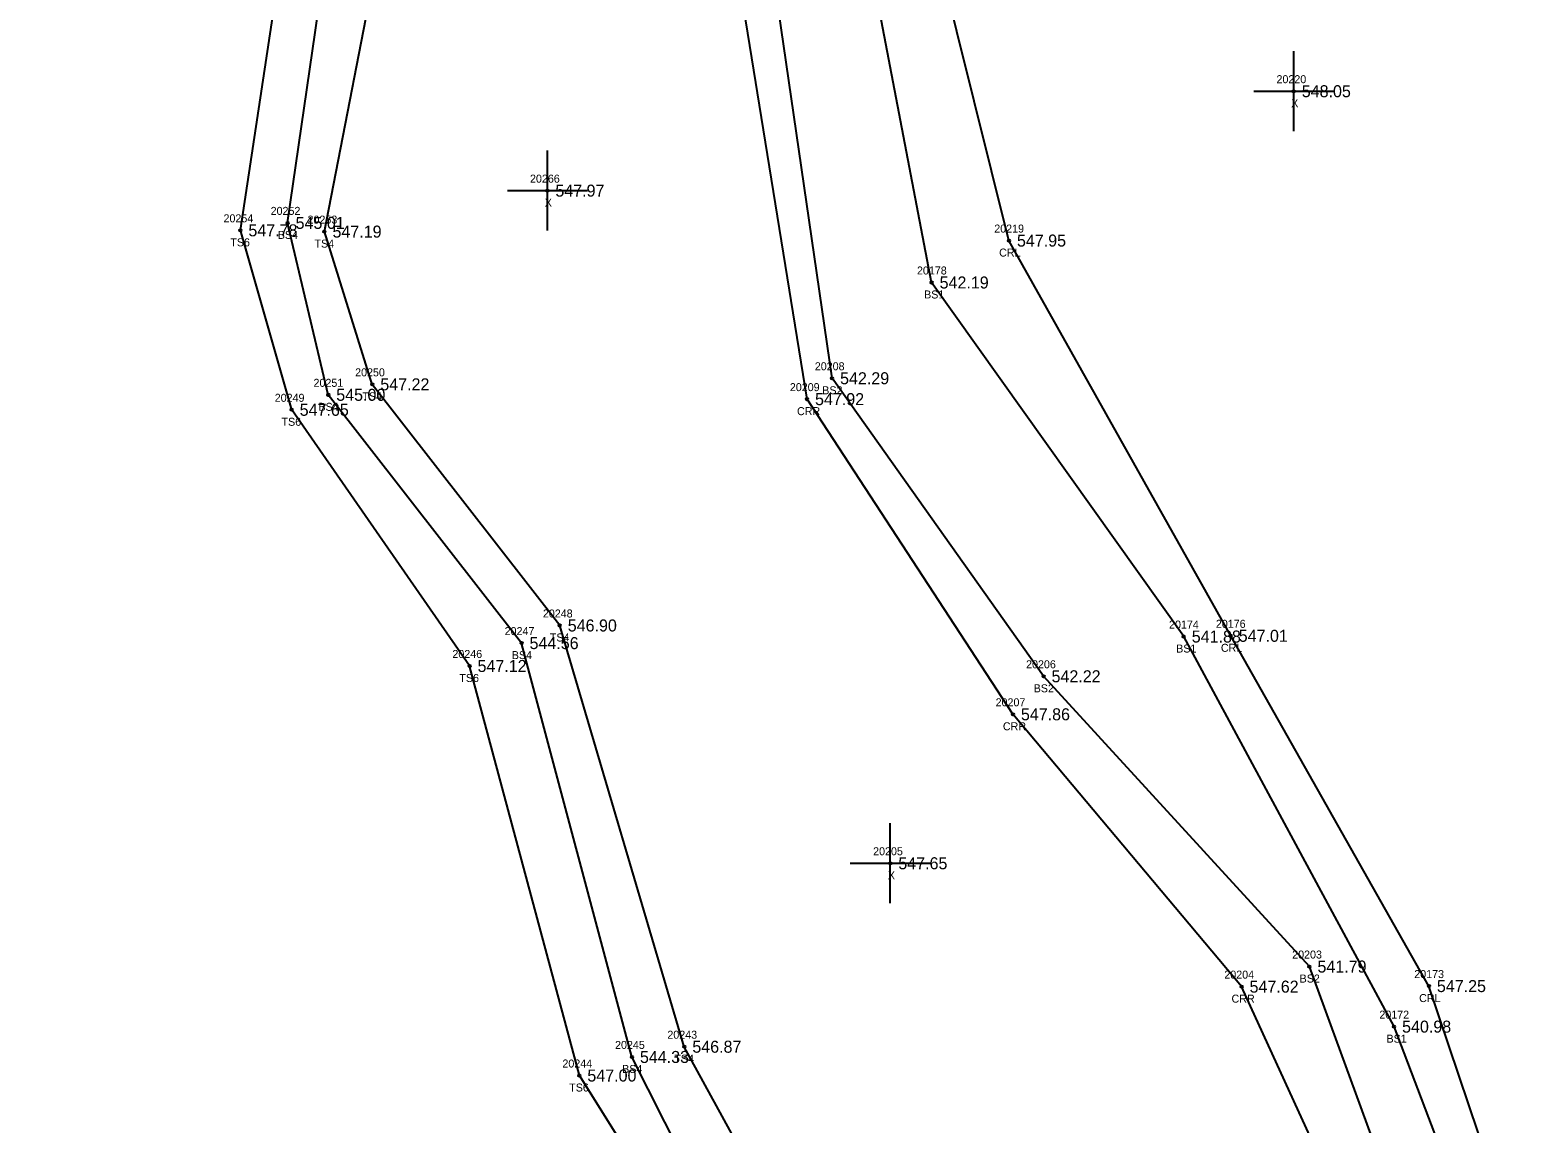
# Model space of a CAD drawing. Extents: x 1540443 to 1541844, y 887157 to 888162.
# Drawn here: x 1540989.1 to 1541174.7, y 887893.1 to 888029.8 of the extents above; entities that cross this region are included whole.
import ezdxf

# ---------------------------------------------------------------- set-up
doc = ezdxf.new("R2010")
doc.units = 0
for name, color, linetype in [('RD_DTM_BkLn2', 7, 'Continuous'), ('RD_DTM_BkLn_txCode', 7, 'Continuous'), ('RD_EX_H2O', 7, 'Continuous'), ('RD_EX_H2O_txCode', 7, 'Continuous'), ('RD_EX_Misc', 7, 'Continuous'), ('RD_EX_Misc_txCode', 7, 'Continuous'), ('RD_EX_TX_H2O_ELEV', 7, 'Continuous'), ('RD_EX_TX_Misc_ELEV', 7, 'Continuous'), ('RD_SMD_Locator', 7, 'Continuous')]:
    doc.layers.add(name, color=color, linetype=linetype)

msp = doc.modelspace()

# ---------------------------------------------------------------- linework, layer by layer
at = {"layer": 'RD_DTM_BkLn2'}
for points in [[(1541349.06, 887859.41), (1541301.9, 887838.51), (1541276.98, 887854.12), (1541250.17, 887847.68), (1541235.42, 887838.4), (1541226.46, 887818.66), (1541206.99, 887816.69), (1541177.91, 887783.05), (1541174.61, 887756.9), (1541155.39, 887744.58), (1541154.65, 887729.69), (1541126.74, 887754.56), (1541108.32, 887769.11), (1541148.46, 887831.42), (1541178.11, 887856.6), (1541159.66, 887905.22), (1541133.37, 887953.98), (1541101.85, 887998.23), (1541093.93, 888039.66), (1541072.92, 888058.86), (1541087, 888085), (1541104.04, 888122.31), (1541088.02, 888158.63)], [(1541146.1, 887665.49), (1541138.57, 887693.18), (1541134.72, 887704.76), (1541142.18, 887722.96), (1541114.88, 887744.39), (1541098.19, 887760.21), (1541108.65, 887794.85), (1541126.24, 887822.69), (1541166.01, 887866.51), (1541149.08, 887912.73), (1541115.84, 887949.01), (1541089.41, 887986.26), (1541082.08, 888036.68), (1541064.88, 888057.53), (1541079.32, 888092.84), (1541092.39, 888127.26), (1541076.18, 888157.56)], [(1541109.47, 887816.01), (1541103.08, 887823.18), (1541089.58, 887845.5), (1541085.67, 887875.78), (1541070.94, 887902.71), (1541055.37, 887955.36), (1541031.94, 887985.5), (1541025.96, 888004.59), (1541033.15, 888041.73), (1541003.69, 888062.03), (1540999.11, 888100.69)], [(1541106.04, 887811.91), (1541099.17, 887816.32), (1541082.8, 887844.85), (1541076.7, 887877.04), (1541064.39, 887901.43), (1541050.59, 887953.16), (1541026.43, 887984.19), (1541021.35, 888005.68), (1541026.22, 888039.26), (1540998.69, 888058.54), (1540993.78, 888096.72)], [(1541097.04, 887797.31), (1541091.49, 887816.39), (1541076.38, 887843.69), (1541072.19, 887876.18), (1541057.82, 887899.11), (1541044.09, 887950.3), (1541021.86, 887982.32), (1541015.45, 888004.75), (1541020.24, 888036.52), (1540992.24, 888055.16), (1540989.11, 888091.69)]]:
    msp.add_lwpolyline(points, dxfattribs=at)
at = {"layer": 'RD_EX_H2O'}
for points in [[(1541345.47, 887860.33), (1541299.81, 887843.04), (1541278.31, 887858.39), (1541248.14, 887850.88), (1541232.97, 887840.42), (1541206.44, 887819.7), (1541175.27, 887783.56), (1541168.89, 887762.72), (1541151.82, 887746.65), (1541151.42, 887737.55), (1541129.57, 887759.43), (1541125.03, 887781.17), (1541150.06, 887828.48), (1541182.67, 887854.92), (1541164.01, 887910.29), (1541139.24, 887954.07), (1541111.52, 888003.47), (1541100.67, 888047.04), (1541091.5, 888080.23), (1541107.64, 888120.67), (1541095.14, 888160.09)], [(1541139.32, 887662.55), (1541132.94, 887692.98), (1541127.99, 887710.83), (1541127.84, 887719.69), (1541112.29, 887736.27), (1541094.28, 887759.52), (1541097.04, 887797.31), (1541106.04, 887811.91), (1541109.47, 887816.01), (1541121.03, 887830.67), (1541155.26, 887878.19), (1541140.59, 887910.22), (1541112.01, 887944.26), (1541086.28, 887983.65), (1541077.88, 888035.59), (1541062.25, 888056.78), (1541074.93, 888096.19), (1541086.66, 888128.26), (1541074.68, 888157.66)]]:
    msp.add_lwpolyline(points, dxfattribs=at)
at = {"layer": 'RD_EX_Misc'}
for p, q in [((1541147.12, 888017.14), (1541147.12, 888027.14)), ((1541142.12, 888022.14), (1541152.12, 888022.14)), ((1541053.82, 888004.71), (1541053.82, 888014.71)), ((1541048.82, 888009.71), (1541058.82, 888009.71)), ((1541096.69, 887920.64), (1541096.69, 887930.64)), ((1541091.69, 887925.64), (1541101.69, 887925.64))]:
    msp.add_line(p, q, dxfattribs=at)
at = {"layer": 'RD_SMD_Locator'}
for centre in [(1541147.12, 888022.14), (1541053.82, 888009.71), (1541021.35, 888005.68), (1541015.45, 888004.75), (1541025.96, 888004.59), (1541111.52, 888003.47), (1541101.85, 887998.23), (1541031.94, 887985.5), (1541089.41, 887986.26), (1541026.43, 887984.19), (1541086.28, 887983.65), (1541021.86, 887982.32), (1541055.37, 887955.36), (1541133.37, 887953.98), (1541139.24, 887954.07), (1541050.59, 887953.16), (1541044.09, 887950.3), (1541115.84, 887949.01), (1541112.01, 887944.26), (1541096.69, 887925.64), (1541149.08, 887912.73), (1541140.59, 887910.22), (1541164.01, 887910.29), (1541159.66, 887905.22), (1541064.39, 887901.43), (1541070.94, 887902.71), (1541057.82, 887899.11)]:
    msp.add_circle(centre, 0.15, dxfattribs=at)

# ---------------------------------------------------------------- texts
at = {"layer": 'RD_DTM_BkLn_txCode'}
for s, p in [('20252', (1541019.23, 888006.68)), ('20254', (1541013.34, 888005.75)), ('20253', (1541023.84, 888005.59)), ('TS6', (1541014.19, 888002.75)), ('BS4', (1541020.12, 888003.68)), ('TS4', (1541024.71, 888002.59)), ('20178', (1541100.02, 887999.23)), ('BS1', (1541100.91, 887996.23)), ('20250', (1541029.79, 887986.5)), ('20208', (1541087.25, 887987.26)), ('20251', (1541024.59, 887985.19)), ('BS2', (1541088.18, 887984.26)), ('20249', (1541019.74, 887983.32)), ('BS4', (1541025.2, 887982.19)), ('TS4', (1541030.7, 887983.5)), ('TS6', (1541020.59, 887980.32)), ('20248', (1541053.26, 887956.36)), ('20174', (1541131.53, 887954.98)), ('20247', (1541048.48, 887954.16)), ('TS4', (1541054.13, 887953.36)), ('20246', (1541041.95, 887951.3)), ('BS4', (1541049.37, 887951.16)), ('BS1', (1541132.42, 887951.98)), ('20206', (1541113.66, 887950.01)), ('TS6', (1541042.82, 887948.3)), ('BS2', (1541114.61, 887947.01)), ('20203', (1541146.92, 887913.73)), ('BS2', (1541147.85, 887910.73)), ('20172', (1541157.82, 887906.22)), ('20245', (1541062.28, 887902.43)), ('20243', (1541068.82, 887903.71)), ('BS1', (1541158.71, 887903.22)), ('TS4', (1541069.69, 887900.71)), ('20244', (1541055.7, 887900.11)), ('BS4', (1541063.17, 887899.43)), ('TS6', (1541056.55, 887897.11))]:
    msp.add_text(s, height=1, dxfattribs=at).set_placement(p)
at = {"layer": 'RD_EX_H2O_txCode'}
for s, p in [('20219', (1541109.68, 888004.47)), ('CRL', (1541110.29, 888001.47)), ('20209', (1541084.13, 887984.65)), ('CRR', (1541085.03, 887981.65)), ('20176', (1541137.38, 887955.07)), ('CRL', (1541138.01, 887952.07)), ('20207', (1541109.85, 887945.26)), ('CRR', (1541110.76, 887942.26)), ('20204', (1541138.44, 887911.22)), ('20173', (1541162.18, 887911.29)), ('CRR', (1541139.34, 887908.22)), ('CRL', (1541162.79, 887908.29))]:
    msp.add_text(s, height=1, dxfattribs=at).set_placement(p)
at = {"layer": 'RD_EX_Misc_txCode'}
for s, p in [('20220', (1541144.96, 888023.14)), ('X', (1541146.8, 888020.14)), ('20266', (1541051.65, 888010.71)), ('X', (1541053.5, 888007.71)), ('20205', (1541094.54, 887926.64)), ('X', (1541096.38, 887923.64))]:
    msp.add_text(s, height=1, dxfattribs=at).set_placement(p)
at = {"layer": 'RD_EX_TX_H2O_ELEV'}
for s, p in [('547.95', (1541112.52, 888002.72)), ('547.92', (1541087.28, 887982.9)), ('547.01', (1541140.24, 887953.32)), ('547.86', (1541113.01, 887943.51)), ('547.62', (1541141.59, 887909.47)), ('547.25', (1541165.01, 887909.54))]:
    msp.add_text(s, height=1.5, dxfattribs=at).set_placement(p)
at = {"layer": 'RD_EX_TX_Misc_ELEV'}
for s, p in [('548.05', (1541148.12, 888021.39)), ('547.97', (1541054.82, 888008.96)), ('547.78', (1541016.45, 888004)), ('545.01', (1541022.35, 888004.93)), ('547.19', (1541026.96, 888003.84)), ('542.19', (1541102.85, 887997.48)), ('542.29', (1541090.41, 887985.51)), ('547.22', (1541032.94, 887984.75)), ('545.00', (1541027.43, 887983.44)), ('547.65', (1541022.86, 887981.57)), ('546.90', (1541056.37, 887954.61)), ('544.56', (1541051.59, 887952.41)), ('541.88', (1541134.37, 887953.23)), ('547.12', (1541045.09, 887949.55)), ('542.22', (1541116.84, 887948.26)), ('547.65', (1541097.69, 887924.89)), ('541.79', (1541150.08, 887911.98)), ('540.98', (1541160.66, 887904.47)), ('546.87', (1541071.94, 887901.96)), ('544.33', (1541065.39, 887900.68)), ('547.00', (1541058.82, 887898.36))]:
    msp.add_text(s, height=1.5, dxfattribs=at).set_placement(p)

doc.saveas('drawing.dxf')
